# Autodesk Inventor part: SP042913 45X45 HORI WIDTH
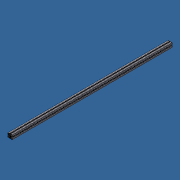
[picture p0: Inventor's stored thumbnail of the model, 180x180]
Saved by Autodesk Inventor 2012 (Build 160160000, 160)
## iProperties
Created: 2013-04
Part Number: SP042913 45X45 HORI WIDTH
Material: Aluminum-6061
Description: PROFILE 45X45 F
Document SubType Name: Modeling
Designer: Admin
Stock Number: 20.1033 PROFILE 45X45 F
Density: 2.71 g/cm^3
FINISH: CLEAR ANODIZED
Author: Admin
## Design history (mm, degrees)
sketch "Sketch1"
  geometry: L1 (-4.1, -22.5)-(-4.1, -18) reference; L2 (-4.6, -18)-(-6.8, -18) reference; L3 (-6.8, -18)-(-6.8, -9.5) reference; L4 (-6.8, -9.5)-(-4.5, -7.2) reference; L5 (-4.5, -7.2)-(4.5, -7.2) reference; L6 (4.5, -7.2)-(6.8, -9.5) reference; L7 (6.8, -9.5)-(6.8, -18) reference; L8 (4.1, -18)-(4.1, -22.5) reference; L9 (22.5, -4.1)-(18, -4.1) reference; L10 (18, -4.6)-(18, -6.8) reference; L11 (18, -6.8)-(9.5, -6.8) reference; L12 (9.5, -6.8)-(7.2, -4.5) reference; L13 (7.2, -4.5)-(7.2, 4.5) reference; L14 (7.2, 4.5)-(9.5, 6.8) reference; L15 (9.5, 6.8)-(18, 6.8) reference; L16 (18, 4.1)-(22.5, 4.1) reference; L17 (22.5, 22.5)-(22.5, 4.4) reference; L18 (4.1, 22.5)-(4.1, 18) reference; L19 (4.6, 18)-(6.8, 18) reference; L20 (6.8, 18)-(6.8, 9.5) reference; L21 (6.8, 9.5)-(4.5, 7.2) reference; L22 (4.5, 7.2)-(-4.5, 7.2) reference; L23 (-4.5, 7.2)-(-6.8, 9.5) reference; L24 (-6.8, 9.5)-(-6.8, 18) reference; L25 (-4.1, 18)-(-4.1, 22.5) reference; L26 (-22.5, 22.5)-(-4.4, 22.5) reference; L27 (-22.5, 4.1)-(-18, 4.1) reference; L28 (-18, 6.8)-(-9.5, 6.8) reference; L29 (-9.5, 6.8)-(-7.2, 4.5) reference; L30 (-7.2, 4.5)-(-7.2, -4.5) reference; L31 (-7.2, -4.5)-(-9.5, -6.8) reference; L32 (-9.5, -6.8)-(-18, -6.8) reference; L33 (-18, -6.8)-(-18, -4.6) reference; L34 (-18, -4.1)-(-22.5, -4.1) reference; L35 (-22.5, -22.5)-(-22.5, -4.4) reference; L36 (-4.4, -22.5)-(-22.5, -22.5) reference; L37 (-4.596, -3.182)-(-3.263, -1.849) reference; L38 (-3.263, 1.849)-(-4.596, 3.182) reference; L39 (-4.596, 3.182)-(-3.182, 4.596) reference; L40 (-3.182, 4.596)-(-1.849, 3.263) reference; L41 (1.849, 3.263)-(3.182, 4.596) reference; L42 (3.182, 4.596)-(4.596, 3.182) reference; L43 (4.596, 3.182)-(3.263, 1.849) reference; L44 (3.263, -1.849)-(4.596, -3.182) reference; L45 (4.596, -3.182)-(3.182, -4.596) reference; L46 (3.182, -4.596)-(1.849, -3.263) reference; L47 (-1.849, -3.263)-(-3.182, -4.596) reference; L48 (-3.182, -4.596)-(-4.596, -3.182) reference; L49 (13.8, -8.8)-(20.5, -8.8) reference; L50 (20.5, -8.8)-(20.5, -15.5) reference; L51 (15.5, -20.5)-(8.8, -20.5) reference; L52 (8.8, -20.5)-(8.8, -13.8) reference; L53 (8.8, 13.8)-(8.8, 20.5) reference; L54 (8.8, 20.5)-(15.5, 20.5) reference; L55 (20.5, 15.5)-(20.5, 8.8) reference; L56 (20.5, 8.8)-(13.8, 8.8) reference; L57 (-13.8, 8.8)-(-20.5, 8.8) reference; L58 (-20.5, 8.8)-(-20.5, 15.5) reference; L59 (-15.5, 20.5)-(-8.8, 20.5) reference; L60 (-8.8, 20.5)-(-8.8, 13.8) reference; L61 (-8.8, -13.8)-(-8.8, -20.5) reference; L62 (-8.8, -20.5)-(-15.5, -20.5) reference; L63 (-20.5, -15.5)-(-20.5, -8.8) reference; L64 (-20.5, -8.8)-(-13.8, -8.8) reference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; A1 r 3.75 centre (0, 0) between (3.362, -1.66) and (3.362, 1.66) reference; A2 r 5 centre (13.8, -13.8) between (13.8, -8.8) and (8.8, -13.8) reference; A3 r 5 centre (15.5, -15.5) between (15.5, -20.5) and (20.5, -15.5) reference; A4 r 5 centre (13.8, 13.8) between (8.8, 13.8) and (13.8, 8.8) reference; A5 r 5 centre (15.5, 15.5) between (20.5, 15.5) and (15.5, 20.5) reference; A6 r 5 centre (-13.8, 13.8) between (-13.8, 8.8) and (-8.8, 13.8) reference; A7 r 5 centre (-15.5, 15.5) between (-15.5, 20.5) and (-20.5, 15.5) reference; A8 r 5 centre (-13.8, -13.8) between (-8.8, -13.8) and (-13.8, -8.8) reference; A9 r 5 centre (-15.5, -15.5) between (-20.5, -15.5) and (-15.5, -20.5) reference; A10 r 3.75 centre (0, 0) between (3.362, 1.66) and (3.263, 1.849) reference; A11 r 3.75 centre (0, 0) between (1.849, 3.263) and (-1.66, 3.362) reference; A12 r 3.75 centre (0, 0) between (-1.66, 3.362) and (-1.849, 3.263) reference; A13 r 3.75 centre (0, 0) between (-3.263, 1.849) and (-3.263, -1.849) reference; A14 r 3.75 centre (0, 0) between (-1.849, -3.263) and (-1.66, -3.362) reference; A15 r 3.75 centre (0, 0) between (-1.66, -3.362) and (1.849, -3.263) reference; A16 r 3.75 centre (0, 0) between (3.263, -1.849) and (3.362, -1.66) reference
  constraints: 160 end point, 32 point on circle, 30 horizontal, 30 vertical, 16 centre point, 144 other
extrude "Extrusion1" new body sketch "Sketch1" stored distance "d0" = 1688 (computed from Width, TOP_OVERHANG); taper "d1" = 0 deg
body "Solid1"
other parameters: "Height" = 1066.8 [user parameter], "Width" = 1828.8 [user parameter; used in 1 equation term], "DEPTH" = 914.4 [user parameter], "LOWER_INSET" = 203.2 [user parameter], "TABLE_TOP_THICKNESS" = 12.7 [user parameter], "LEVELER_HEIGHT" = 44.45 [user parameter], "TOP_OVERHANG" = 25.4 [user parameter; used in 1 equation term]
